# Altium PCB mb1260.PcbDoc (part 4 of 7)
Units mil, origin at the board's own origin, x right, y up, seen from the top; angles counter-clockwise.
Board outline 3189.01 x 3818.89 mil, 6 copper layers (TOP, L2_GND, L3_VCC, L4_SIG, L5_GND, BOTTOM), stack 62.2 mil thick; 308 components, 287 nets, 1220 pads, 851 vias.
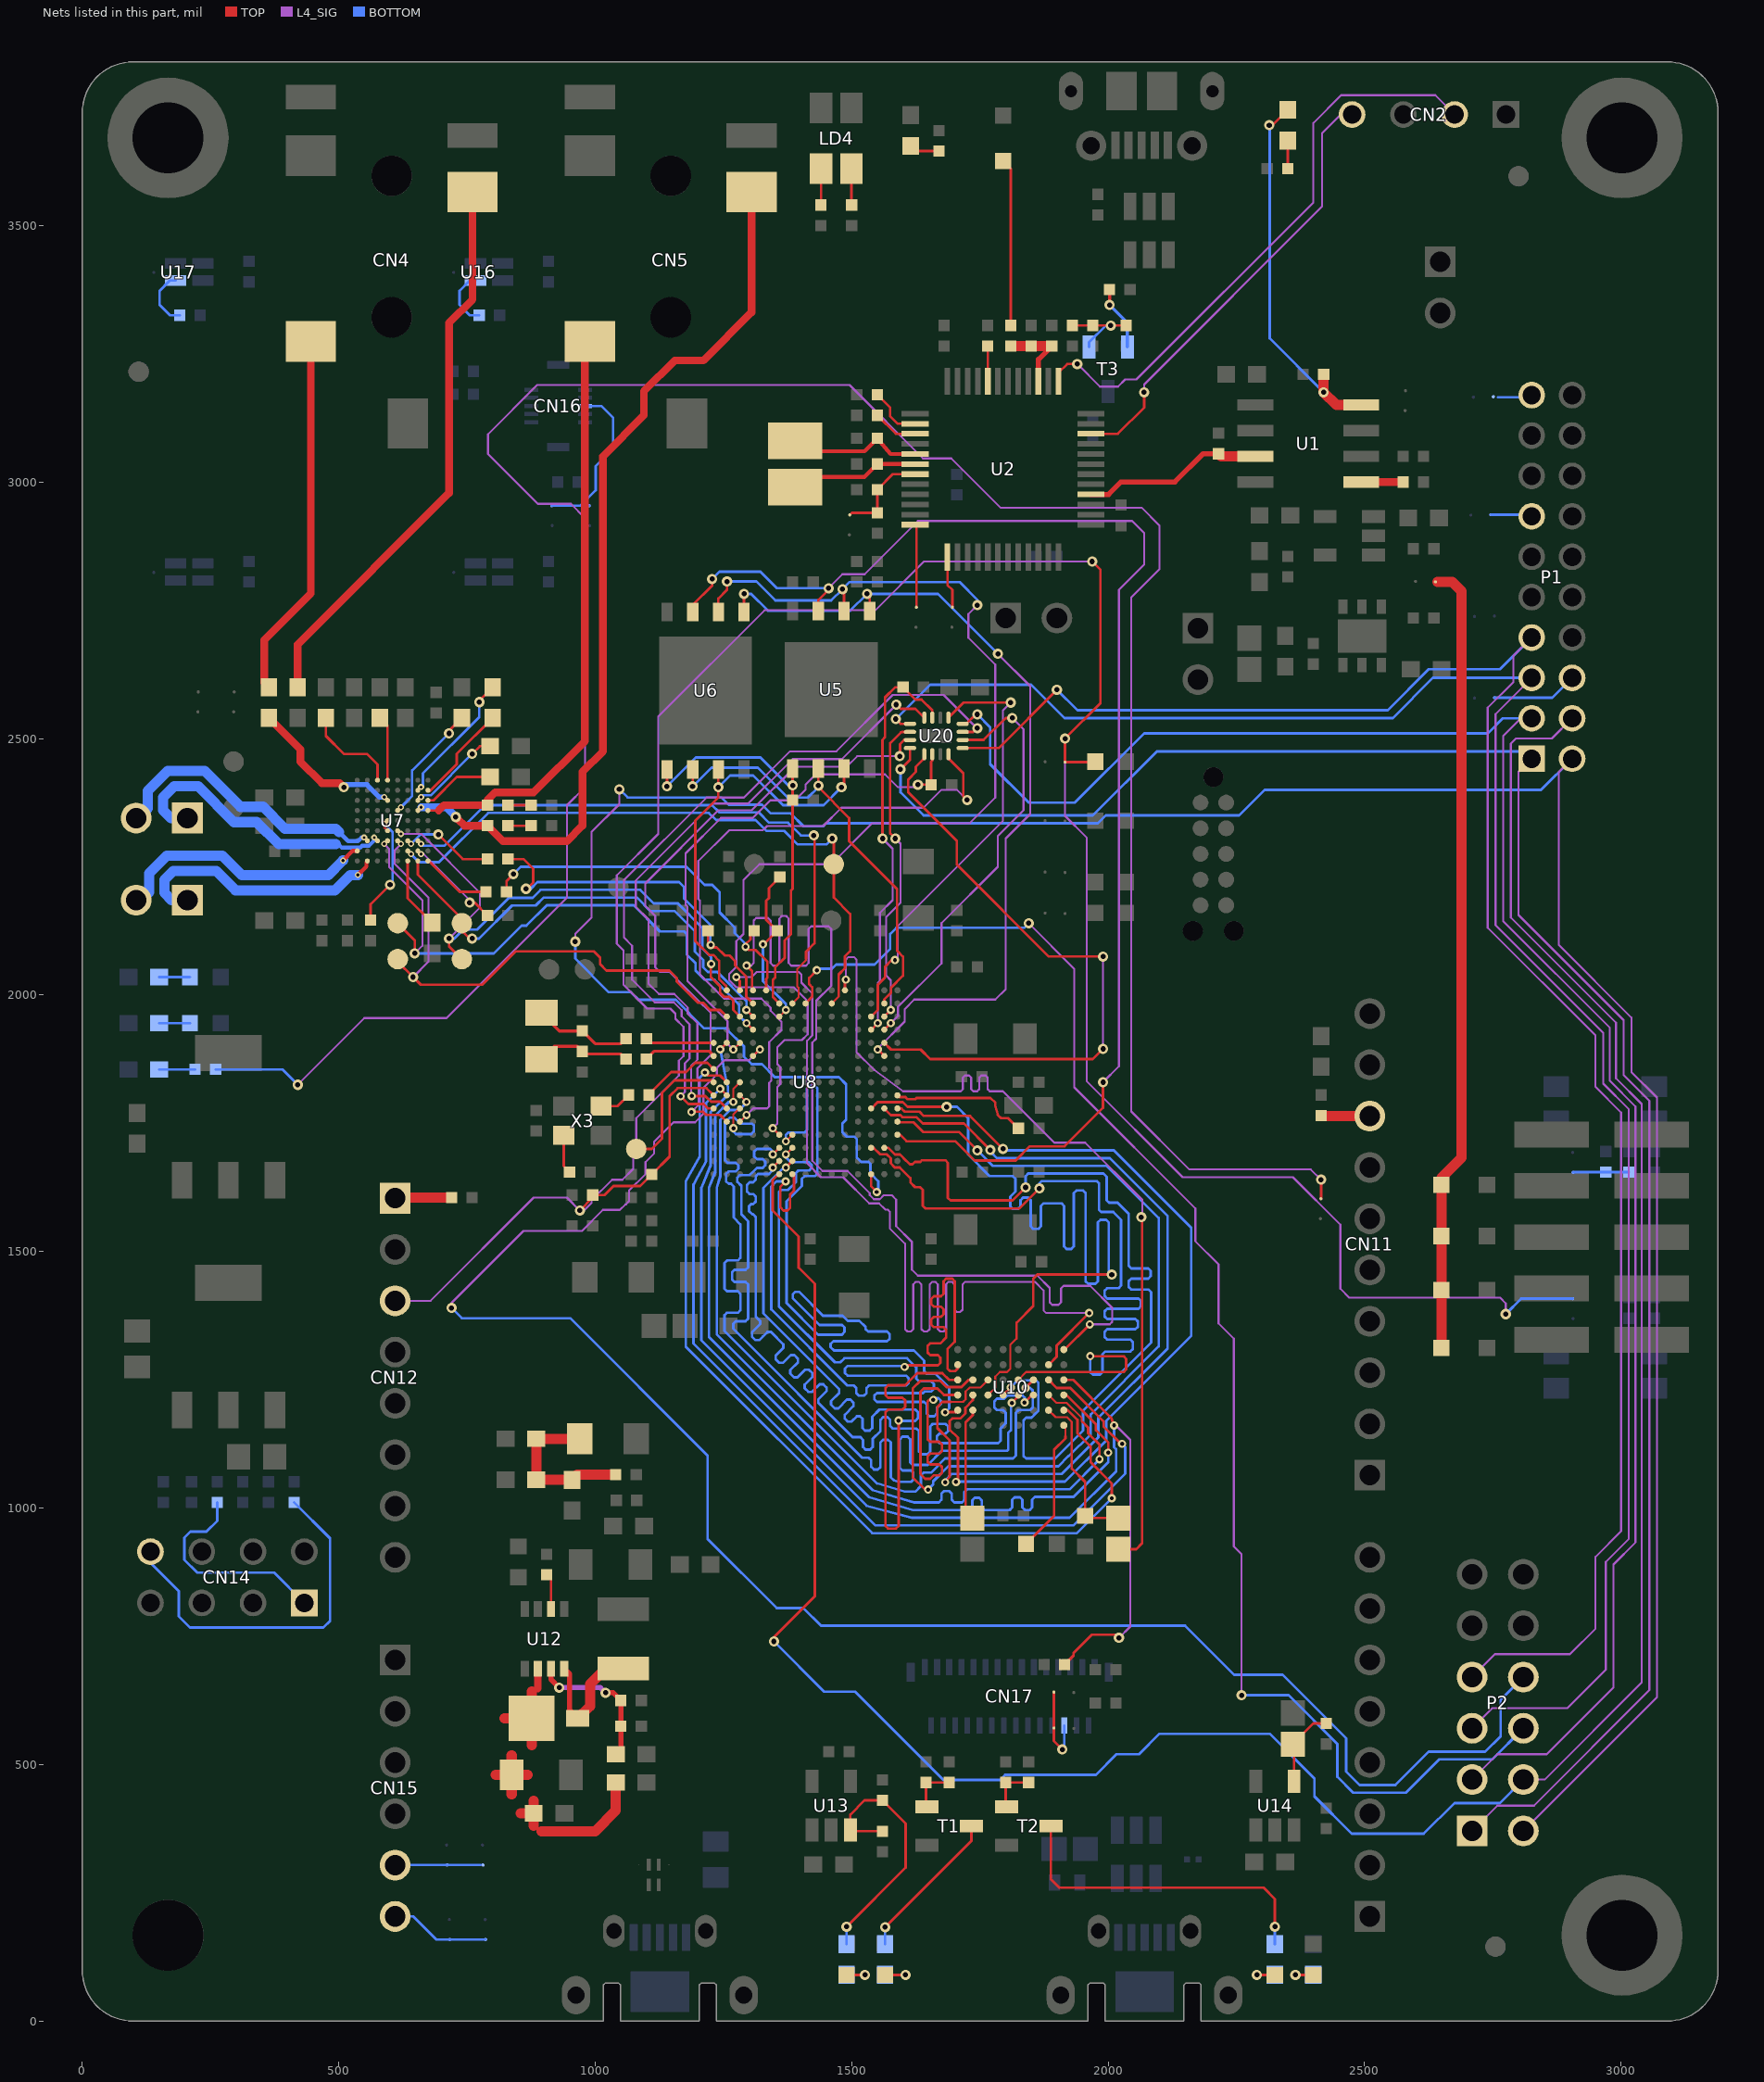
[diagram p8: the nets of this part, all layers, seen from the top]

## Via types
v1: diameter 24, hole 12, TOP to BOTTOM, tented both sides, 389 vias
v2: diameter 20, hole 10, TOP to BOTTOM, tented both sides, 231 vias
v3: diameter 16, hole 8, TOP to BOTTOM, tented both sides, 196 vias
v4: diameter 12, hole 6, TOP to BOTTOM, tented both sides, 35 vias

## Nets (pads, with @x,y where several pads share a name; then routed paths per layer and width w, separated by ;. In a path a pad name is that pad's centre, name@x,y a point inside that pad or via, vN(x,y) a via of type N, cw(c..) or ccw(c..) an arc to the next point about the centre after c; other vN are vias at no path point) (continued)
NETC18_2: C18.2 CN4.4 | length 1106.2
  TOP w15: C18.2@420,2600 420,2683.37 715,2978.37 715,3310 760.63,3355.63 CN4.4@760.63,3565.11
NETC19_2: C19.2 U7.C9 | length 189.2
  TOP w5: C19.2@475,2540 475,2505 510,2470 555,2470 575.47,2449.53 U7.C9@575.47,2418.74
NETC21_1: C21.1 U7.D9 | length 127.5
  TOP w5: C21.1@580,2540 595.16,2524.84 U7.D9@595.16,2418.74
NETC24_1: C24.1 U7.E6 | length 232.2
  TOP w5: U7.E6@614.84,2359.69 v4(621.14,2365.99) ; v2(715,2510) 715,2515 C24.1@740,2540
  BOTTOM w5: v4(621.14,2365.99) 643,2387.85 643,2438 v2(715,2510)
NETC25_1: C25.1 U7.H8 | length 196.2
  TOP w5: U7.H8@673.9,2399.06 679.06,2399.06 730,2450 730,2470 C25.1@800,2540
NETC25_2: C25.2 U7.G8 | length 261.3
  TOP w5: U7.G8@654.21,2399.06 v4(660.51,2405.36) ; v2(774,2571) 774,2574 C25.2@800,2600
  BOTTOM w5: v4(660.51,2405.36) 664.05,2408.9 664.05,2432.05 774,2542 v2(774,2571)
NETC26_1: C26.1 U7.G7 | length 184.5
  TOP w5: U7.G7@654.21,2379.37 v4(660.51,2385.67) ; v2(760,2470) 775,2485 C26.1@795,2485
  BOTTOM w5: v4(660.51,2385.67) 664.06,2389.22 679.22,2389.22 v2(760,2470)
NETC27_1: C27.1 U7.D7 | length 315.9
  TOP w5: v4(588.86,2385.67) U7.D7@595.16,2379.37
  TOP w15: C27.1@364,2540 425,2479 425,2455 467,2413 502,2413 v2(510,2405)
  BOTTOM w10: v2(510,2405) 515,2410 555,2410 579.33,2385.67 v4(588.86,2385.67)
NETC27_2: C27.2 CN4.6 | length 715.1
  TOP w15: C27.2@364,2600 355,2609 355,2692 445.67,2782.67 CN4.6@445.67,3273.78
NETC28_1: C28.1 U7.H7 | length 140
  TOP w5: U7.H7@673.9,2379.37 684.37,2379.37 730,2425 C28.1@795,2425
NETC30_1: C30.1 CN5.6 U7.H6 | length 1150.8
  TOP w5: U7.H6@673.9,2359.69 694.69,2359.69
  TOP w15: 694.69,2359.69 705,2370 C30.1@790,2370 790,2380 805,2395 880,2395 980,2495 980,3264.1 CN5.6@989.68,3273.78
NETC30_2: C30.2 R31.1 | length 45
  TOP w5: C30.2@830,2370 R31.1@875,2370
NETC32_1: C32.1 CN5.4 U7.G6 | length 1761.1
  TOP w5: U7.G6@654.21,2359.69 v4(660.51,2365.99)
  TOP w15: v2@732.57,2342.43 745,2330 C32.1@790,2330 820,2300 945,2300 975,2330 975,2435 1015,2475 1015,3050 1095,3130 1095,3177 1155,3237 1211,3237 1304.64,3330.64 CN5.4@1304.64,3565.11
  BOTTOM w15: v4(660.51,2365.99) 709.01,2365.99 v2(728,2347)
NETC32_2: C32.2 R33.1 | length 45
  TOP w5: C32.2@830,2330 R33.1@875,2330
NETC43_2: C43.2 U7.F1 | length 139.9
  TOP w5: U7.F1@634.53,2261.26 634.53,2188.47 C43.2@682,2141
NETC48_2: C48.2 R49.1 X2.1 | length 194.1
  TOP w6: X2.1@895,1965.28 930.28,1930 C48.2@975,1930 1000,1905 1050,1905 R49.1@1060,1915
NETC51_2: C51.2 R50.1 X2.2 | length 185.8
  TOP w6: X2.2@895,1874.72 920.28,1900 965,1900 C51.2@975,1890 980,1885 1050,1885 R50.1@1060,1875
NETC67_1: C67.1 C69.2 L2.2 L3.2 L4.1 | length 324.1
  TOP w20: C67.1@970,1135 L2.2@885,1135 L3.2@885,1055 L4.1@955,1055 965,1065 C69.2@1040,1065
NETC75_2: C75.2 C76.2 L8.1 U12.6 Z1.2 | length 625
  TOP w15: 888.2,648.2 U12.6@888.2,686.93
  TOP w20: 805.98,480 C75.2@837,480 ; 822.98,590 Z1.2@876,590 ; 837,441.98 C75.2@837,480 ; 837,518.02 C75.2@837,480 ; 854.48,405 C76.2@880,405 ; 868.02,480 C75.2@837,480 ; 876,537.48 Z1.2@876,590 ; 876,642.52 Z1.2@876,590 ; 880,380.98 C76.2@880,405 ; 880,429.02 C76.2@880,405 ; 895,370 1000,370 1040,410 L8.1@1040,465
NETC86_2: C86.2 R90.1 SB33.2 | length 109.2
  BOTTOM w5: SB33.2@2906.19,1654.17 2907.02,1655 C86.2@2970,1655 R90.1@3015,1655
NETCN7_1: CN7.1 U7.C3 | length 568.3
  TOP w5: v4(569.17,2306.93) U7.C3@575.47,2300.63
  BOTTOM w8: 494.4,2294.1 496.79,2294.1 ; 497.4,2293.49 499.59,2293.49 506.05,2287.03 542.03,2287.03 545.66,2290.66 558.54,2290.66 569.17,2301.29 v4(569.17,2306.93)
  BOTTOM w20: CN7.1@205,2345 172.57,2345 157.79,2359.78 157.79,2385.42 179.06,2406.69 226.31,2406.69 296,2337 340,2337 382.9,2294.1 494.4,2294.1
NETCN7_2: CN7.2 U7.B3 | length 570.6
  TOP w5: v4(549.49,2306.93) U7.B3@555.79,2300.63
  BOTTOM w8: 501,2317.4 518.43,2299.97 537.49,2299.97 544.45,2306.93 v4(549.49,2306.93)
  BOTTOM w20: CN7.2@105,2345 108.91,2345 127.89,2363.98 127.89,2397.81 166.67,2436.59 238.7,2436.59 308.39,2366.9 352.39,2366.9 395.29,2324 494.4,2324 501,2317.4
NETCN10_1: CN10.1 U7.B1 | length 524.1
  TOP w8: v4(537.4,2233.87) 553.9,2250.37 553.9,2259.37 U7.B1@555.79,2261.26
  BOTTOM w20: CN10.1@205,2185 174,2185 160,2199 160,2224.71 177.29,2242 261,2242 298.9,2204.1 492.48,2204.1 522.25,2233.87 v4(537.4,2233.87)
NETCN10_2: CN10.2 U7.A2 | length 524
  TOP w8: v4(508.35,2262.34) 526.95,2280.94 U7.A2@536.1,2280.94
  BOTTOM w20: CN10.2@105,2185 115,2185 130.1,2200.1 130.1,2237.1 164.9,2271.9 273.39,2271.9 311.29,2234 480.09,2234 v4(508.35,2262.34) v4(508.35,2262.34)
NETCN11_8: CN11.8 R53.1 | length 95.3
  TOP w20: R53.1@2415,1765 2416.06,1763.94 CN11.8@2509.84,1763.94
NETCN12_1: CN12.1 R58.1 | length 110.6
  TOP w20: CN12.1@609.84,1603.94 610.9,1605 R58.1@720,1605
NETCN14_1: CN14.1 R92.2 | length 425.5
  BOTTOM w5: R92.2@263,1011 263,975 242,954 211,954 199,942 199,899 224,874 373.99,874 CN14.1@432.99,815
NETCN14_8: CN14.8 R97.1 | length 718.3
  BOTTOM w5: CN14.8@132.99,915 132.99,893.01 188,838 188,789 210,767 470,767 483,780 483,941 R97.1@413,1011
NETCN15_5: CN15.5 SB35.2 SB36.2 | length 166.4
  BOTTOM w5: CN15.5@609.84,303.94 610.07,304.17 SB36.2@711.19,304.17 776.19,304.17
NETCN15_6: CN15.6 SB37.2 SB38.2 | length 195.2
  BOTTOM w5: CN15.6@609.84,203.94 645,203.94 689.91,159.03 SB38.2@716.39,159.03 SB37.2@786.39,159.03
NETCN16_8: CN16.8 SB2.1 SB4.1 | length 335.5
  BOTTOM w5: SB2.1@915.17,2953.77 970.85,2953.77 ; CN16.8@979.91,3148.16 1011.84,3148.16 1035,3125 1035,3065 1000.84,3030.84 1000.84,2983.76 970.85,2953.77 ; SB4.1@988.17,2953.77 970.85,2953.77
NETCN17_24: CN17.24 SB15.2 SB16.2 | length 166.6
  TOP w5: SB15.2@1894.17,641.19 SB16.2@1894.17,571.19 1894.17,545.83 v2(1910.55,529.45)
  BOTTOM w5: v2(1910.55,529.45) 1914.45,533.35 CN17.24@1914.45,575.91
NETD1_2: D1.2 R4.2 | length 326.9
  TOP w5: D1.2@1795,3625.71 1810,3610.71 R4.2@1810,3305
NETD2_2: D2.2 D3.2 D4.2 D5.2 SB7.1 | length 1545.5
  TOP w20: 2642.33,2805.33 2670.67,2805.33 2689,2787 2689,1683 2649.71,1643.71 D5.2@2649.71,1630 D4.2@2649.71,1530 D3.2@2649.71,1425 D2.2@2649.71,1312
NETL6_2: L6.2 U12.8 Z1.1 | length 262.3
  TOP w10: U12.8@939.39,686.93 950,676.32 950,606 Z1.1@966,590
  TOP w20: Z1.1@966,590 990,614 990,657 1020,687 L6.2@1055,687
NETL7_2: L7.2 R69.2 R71.2 U12.7 | length 283.1
  TOP w10: U12.7@913.8,686.93 913.8,666.2 v2(930,650) ; v2(1020,640) 1035,640 R69.2@1050,625 R71.2@1050,575 1050,530 L7.2@1040,520
  L4_SIG w10: v2(930,650) 1010,650 v2(1020,640)
NETLD1_1: LD1.1 R12.1 | length 70
  BOTTOM w5: LD1.1@150,1855 R12.1@220,1855
NETLD2_1: LD2.1 R1.2 | length 59.1
  TOP w5: LD2.1@1615,3655 1625,3645 R1.2@1670,3645
NETLD3_1: LD3.1 R2.1 | length 55
  TOP w5: R2.1@2350,3610.59 LD3.1@2350,3665.59
NETLD3_2: LD3.2 R15.1 U1.8 | length 731.6
  TOP w5: v2(2314,3695.59) 2320,3695.59 LD3.2@2350,3725.59
  TOP w20: R15.1@2420,3210 v2(2420,3175) 2445,3150 U1.8@2493.3,3150
  BOTTOM w5: v2(2314,3695.59) 2315,3694.59 2315,3280 v2(2420,3175)
NETLD4_2: LD4.2 R14.2 | length 71.1
  TOP w5: LD4.2@1499.53,3610.94 1499.53,3540.47 R14.2@1500,3540
NETLD4_3: LD4.3 R13.2 | length 71.1
  TOP w5: R13.2@1440,3540 1440.47,3540.47 LD4.3@1440.47,3610.94
NETLD5_1: LD5.1 R47.2 | length 60
  BOTTOM w5: LD5.1@150,2035 R47.2@210,2035
NETLD6_1: LD6.1 R48.2 | length 60
  BOTTOM w5: LD6.1@150,1945 R48.2@210,1945
NETLD7_1: LD7.1 R81.2 | length 72
  TOP w5: R81.2@1490,90 v2(1526,90)
  BOTTOM w5: LD7.1@1490,90 v2(1526,90)
NETLD7_2: LD7.2 R78.1 R80.2 U13.3 | length 513.9
  TOP w5: v2(1490,184) 1605,299 1605,385 R78.1@1560,430 1525,430 1497.4,402.4 U13.3@1497.4,372.76 1499.33,370.38 1499.64,370 R80.2@1560,370
  BOTTOM w5: LD7.2@1490,150 v2(1490,184)
NETLD8_1: LD8.1 R82.1 | length 80
  TOP w5: R82.1@1565,90 v2(1605,90)
  BOTTOM w5: LD8.1@1565,90 v2(1605,90)
NETLD8_2: LD8.2 T1.3 | length 299.7
  TOP w5: v2(1565,183) 1733.31,351.31 T1.3@1733.31,380
  BOTTOM w5: LD8.2@1565,150 v2(1565,183)
NETLD9_1: LD9.1 R83.1 | length 70
  TOP w5: v2(2290,90) R83.1@2325,90
  BOTTOM w5: v2(2290,90) LD9.1@2325,90
NETLD9_2: LD9.2 T2.3 | length 644
  TOP w5: T2.3@1888.31,380 1888.31,276.69 1905,260 2303,260 2325,238 v2(2325,184)
  BOTTOM w5: LD9.2@2325,150 v2(2325,184)
NETLD10_1: LD10.1 R84.1 | length 70
  TOP w5: v2(2365,90) R84.1@2400,90
  BOTTOM w5: v2(2365,90) LD10.1@2400,90
NETR3_2: R3.2 U2.44 | length 68.9
  TOP w5: R3.2@1765,3265 1765.47,3264.53 U2.44@1765.47,3196.26
NETR7_1: R7.1 R8.2 R11.2 T3.1 | length 170.1
  TOP w5: R7.1@1930,3305 R8.2@1970,3305 v2(2005,3305) R11.2@2035,3305
  BOTTOM w5: T3.1@1962.6,3263.31 1962.6,3272.6 1995,3305 v2(2005,3305)
NETR10_1: R10.1 T3.2 | length 126.1
  TOP w6.1: v2(2002.6,3345) R10.1@2002.6,3375
  BOTTOM w6.1: v2(2002.6,3345) 2037.4,3310.2 T3.2@2037.4,3263.31
NETR12_2: R12.2 SB14.1 | length 4971.4
  TOP w5: SB14.1@2415,1603.01 v2(2415,1640)
  L4_SIG w4: v2(420,1825) 550,1955 710,1955 945,2190 945,2370 980,2405 980,2930 952.67,2957.33 888.13,2957.33 790.94,3054.52 790.94,3092.96 886.98,3189 1496,3189 1639,3046 1694,3046 1790,2950 2065,2950 2100,2915 2100,2830 2045,2775 2045,1773 2158,1660 2395,1660 v2(2415,1640)
  BOTTOM w5: R12.2@260,1855 390,1855 v2(420,1825)
NETR17_2: R17.2 U2.2 | length 107.1
  TOP w5: R17.2@1550,3170 1575,3145 1575,3128 1589.42,3113.58 U2.2@1623.74,3113.58
NETR19_2: R19.2 U2.3 | length 88.7
  TOP w5: R19.2@1550,3130 1586.1,3093.9 U2.3@1623.74,3093.9
NETR22_1: R22.1 U1.5 | length 81.7
  TOP w15: U1.5@2493.3,3000 R22.1@2575,3000
NETR35_2: R35.2 U7.F3 | length 185.7
  TOP w5: U7.F3@634.53,2300.63 v4(640.83,2294.33) ; v2(694,2313) 742,2265 R35.2@790,2265
  BOTTOM w5: v4(640.83,2294.33) 659.5,2313 v2(694,2313)
NETR39_2: R39.2 U7.H1 | length 138.1
  TOP w5: U7.H1@673.9,2261.26 675.15,2260.01 676.68,2260.01 735.69,2201 R39.2@787,2201
NETR41_2: R41.2 U7.G2 | length 191
  TOP w5: U7.G2@654.21,2280.94 v4(660.51,2274.64) ; v2(755,2180) 765,2180 R41.2@790,2155
  L4_SIG w4: v4(660.51,2274.64) 665.52,2274.64 755,2185.16 v2(755,2180)
NETR46_1: R46.1 U7.D4 U7.D5 | length 237.1
  TOP w5: R46.1@562,2146 562,2177 v2(600,2215) ; U7.D4@595.16,2320.31 588.85,2326.62 v4(588.85,2333.7) U7.D5@595.16,2340
  BOTTOM w5: v4(588.85,2333.7) 605,2317.55 605,2220 v2(600,2215)
NETR55_2: R55.2 X3.1 | length 76.2
  TOP w5: X3.1@938.58,1726.46 938.58,1666.42 R55.2@950,1655
NETR63_1: R63.1 R65.2 U10.B5 | length 315.2
  TOP w4: U10.B5@1883.82,1190.71 1897.53,1177 1920,1177 1929,1168 1929,1145
  TOP w5: 1929,1145 1929,1077 1955,1051 R63.1@1955,985 1959.49,980.51 R65.2@2020,980.51
NETR64_2: R64.2 U10.G5 | length 221.5
  TOP w5: R64.2@1735,980.51 1722,993.51 1722,1167 1736.18,1181.18 U10.G5@1736.18,1190.71
NETR67_2: R67.2 U12.2 | length 70.6
  TOP w5: R67.2@905,870 913.8,861.2 U12.2@913.8,803.07
NETR72_2: R72.2 R73.1 U14.4 | length 155.3
  TOP w5: U14.4@2362.4,467.24 2362.4,537.09 R72.2@2360,539.49 2360,540 2400,580 R73.1@2425,580
NETR74_1: R74.1 R75.1 T1.1 | length 93.3
  TOP w5: T1.1@1646.69,417.4 1645,419.09 R74.1@1645,465 R75.1@1690,465
NETR76_2: R76.2 R77.1 T2.1 | length 93.3
  TOP w5: T2.1@1801.69,417.4 1800,419.09 R76.2@1800,465 R77.1@1845,465
NETR85_1: R85.1 U16.2 | length 113.7
  BOTTOM w5: U16.2@766.5,3392.68 755.29,3392.68 735.29,3372.68 735.29,3345.32 755.61,3325 R85.1@773.74,3325
NETR86_1: R86.1 U17.2 | length 114.6
  BOTTOM w5: U17.2@181.89,3392.68 170.68,3392.68 150.68,3372.68 150.68,3345.32 171,3325 R86.1@190,3325
NETR100_1: R100.1 U10.A6 | length 264.2
  TOP w4: U10.A6@1913.35,1161.18 1916.5,1158.03 1916.5,1140
  TOP w5: R100.1@1840,930 1894.51,984.51 1894.51,1113.51 1916.5,1135.5 1916.5,1140
NRST: C93.2 CN12.3 R28.2 R57.1 SB10.2 SB34.1 U8.J1 | length 5444.3
  TOP w5: v2(970,1580) 995,1605 C93.2@995,1610 1018.17,1610 1035.67,1627.5 1087.5,1627.5 R57.1@1110,1650 1145,1685 1145,1803 1160.5,1818.5 1216.78,1818.5 U8.J1@1230.87,1804.41 ; v2(1969,2845) 1985,2829 1985,2569.17 v2(1915.83,2500) SB10.2@1915.83,2453.81 1973.81,2453.81 R28.2@1975,2455
  L4_SIG w4: CN12.3@609.84,1403.94 678.94,1403.94 880,1605 945,1605 v2(970,1580) 978.02,1580 993,1594.98 993,1599.98 1033.02,1640 1053.1,1640 1074.03,1660.93 1074.03,1684.09 1080,1690.06 1080,1760 1163,1843 1163,1871.94 1172,1880.94 1172,1938 1156.35,1953.65 1156.35,1963.78 1146.4,1973.73 1101.27,1973.73 1055,2020 1055,2087 1042,2100 1042,2233 1123,2314 1123,2543 1330,2750 1546,2750 1641,2845 v2(1969,2845) ; v2(1915.83,2500) 1915.83,2349.17 1958,2307 1958,1832 2145,1645 2360,1645 2452.5,1552.5 2452.5,1427.5 2470,1410 2764,1410 2775,1399 v2(2775,1378)
  BOTTOM w5: v2(2775,1378) 2805.01,1408.01 SB34.1@2905.33,1408.01
OSC_25M: R51.1 X3.3 | length 62.5
  TOP w5: X3.3@1011.42,1783.54 1043.54,1783.54 R51.1@1065,1805
OSC_IN: C4.2 U2.5 X1.2 | length 266.7
  TOP w8: X1.2@1390,3080.28 1410.28,3060 1525,3060 C4.2@1550,3085 1575.47,3054.53 U2.5@1623.74,3054.53
OSC_OUT: C6.2 U2.6 X1.1 | length 252.5
  TOP w8: X1.1@1390,2989.72 1410,3009.72 1524.72,3009.72 C6.2@1550,3035 1554.84,3034.84 U2.6@1623.74,3034.84
PC14-OSC32_IN: R49.2 U8.E1 | length 134.3
  TOP w6: R49.2@1100,1915 1108.23,1906.77 U8.E1@1230.87,1906.77
PC15-OSC32_OUT: R50.2 U8.F1 | length 141.2
  TOP w6: R50.2@1100,1875 1115.5,1890.5 1221.55,1890.5 U8.F1@1230.87,1881.18
PDRON: R37.2 R45.2 U8.C6 | length 328.5
  TOP w4: U8.C6@1358.82,1957.95 v3(1371.68,1970.81)
  TOP w5: v3(1327,2099) 1329,2099 R45.2@1355,2125 1333.5,2146.5 1333.5,2183.91 1338.5,2188.91 1338.5,2208.5 R37.2@1360,2230
  BOTTOM w5: v3(1327,2099) 1327,2027 1371.68,1982.32 v3(1371.68,1970.81)
PH0-OSCIN: R51.2 U8.G1 | length 158.1
  TOP w5: R51.2@1105,1805 1105,1806.71 1148.29,1850 1177,1850 1195,1868 1218.46,1868 U8.G1@1230.87,1855.59
PH1-OSCOUT: TP15.1 U8.H1 | length 259.9
  TOP w5: TP15.1@1080,1700 1110,1700 1130,1720 1130,1809.22 1154.28,1833.5 1227.37,1833.5 U8.H1@1230.87,1830
PMOD#1: P1.1 P2.1 U20.8 | length 3792.3
  TOP w5: v2(1595,2440) 1613.63,2458.63 U20.8@1613.63,2481.38
  L4_SIG w4: P2.1@2709.33,370.63 2758.7,420 2830,420 3055,645 3055,1793.78 3005,1843.78 3005,1951 2800,2156 2800,2435 P1.1@2825.63,2460.63
  BOTTOM w5: v2(1595,2440) 1595,2395 1640,2350 1970,2350 2095,2475 2811.26,2475 P1.1@2825.63,2460.63
PMOD#2: P1.2 P2.2 U20.16 | length 3697.9
  TOP w5: U20.16@1716.37,2528.62 1723.62,2528.62 1742,2547 v2(1745,2547)
  L4_SIG w4: P2.2@2709.33,470.63 2758.7,520 2855,520 2985,650 2985,890 3028,933 3028,1782.58 2978,1832.58 2978,1936 2770,2144 2770,2505 2804.37,2539.37 P1.2@2825.63,2539.37
  BOTTOM w5: v2(1745,2547) 1770,2522 1770,2450 1845,2375 1935,2375 2070,2510 2740,2510 2769.37,2539.37 P1.2@2825.63,2539.37
PMOD#3: P1.3 P2.3 U20.5 | length 3754.9
  TOP w5: v2(1586,2538) 1595.38,2528.62 U20.5@1613.63,2528.62
  L4_SIG w4: P2.3@2709.33,570.63 2748.7,610 2895,610 2970,685 2970,895 3015,940 3015,1777.19 2965,1827.19 2965,1926 2755,2136 2755,2547.48 P1.3@2825.63,2618.11
  BOTTOM w5: v2(1586,2538) 1653,2605 1850,2605 1915,2540 2555,2540 2633.11,2618.11 P1.3@2825.63,2618.11
PMOD#4: P1.4 P2.4 U20.13 | length 3607.1
  TOP w5: U20.13@1716.37,2481.38 1786.38,2481.38 v2(1900,2595)
  L4_SIG w4: P2.4@2709.33,670.63 2753.7,715 2900,715 2950,765 2950,905 3000,955 3000,1770.97 2950,1820.97 2950,1921 2740,2131 2740,2560 2790,2610 2790,2661.22 P1.4@2825.63,2696.85
  BOTTOM w5: v2(1900,2595) 1940,2555 2545,2555 2625,2635 2763.78,2635 P1.4@2825.63,2696.85
PMOD_GPIO_0: P2.9 U8.B8 | length 2941.3
  TOP w5: U8.B8@1410,1983.54 1423,1996.54 1423,2015 1417,2021 1417,2033 1431.98,2047.98 v3(1431.98,2048.39)
  L4_SIG w4: v2(1845,2140) 1934,2051 1934,1820 2170,1584 2170,1520 2215,1475 2215,1360 2245,1330 2245,925 2260,910 v2(2260,635)
  BOTTOM w5: v3(1431.98,2048.39) 1432.61,2048.39 1435.22,2051 1461,2051 1469.5,2059.5 1544.5,2059.5 1575,2090 1575,2119 1587,2131 1836,2131 v2(1845,2140) ; v2(2260,635) 2352,635 2447,540 2447,476 2478,445 2580,445 2645,510 2748.7,510 P2.9@2809.33,570.63
PMOD_GPIO_1: P2.10 U8.F4 | length 3647.6
  TOP w5: U8.F4@1307.64,1881.18 1308.18,1881.18 v3(1321,1894)
  L4_SIG w4: v2(720,1390) 720,1400 860,1540 974.14,1540 1015.14,1581 1047.88,1581 1059,1592.12 1060,1592.12 1066,1598.12 1066,1618.94 1098.03,1650.97 1098.03,1674.13 1115,1691.1 1115,1714.27 1152.73,1752 1194.61,1752 1211,1768.39 1211,1819 1237,1845 1237,1858 1252,1873 1256.36,1873 1262.99,1873.01 1300,1873 v3(1321,1894)
  BOTTOM w5: v2(720,1390) 740,1370 951,1370 1219,1102 1219,939.78 1353.78,805 1405.78,805 1440.28,770.5 2150,770.5 2245.5,675 2340,675 2464,551 2464,486 2490,460 2560,460 2625,525 2735,525 2765,555 2765,626.3 P2.10@2809.33,670.63
PMOD_INT: P1.11 P2.7 U8.R13 | length 5536.4
  TOP w5: U8.R13@1537.95,1650.87 1537.95,1627.05 v3(1549,1616)
  L4_SIG w4: v2(961,2104) 961,2119 993,2151 993,2318 1047,2372 v2(1047,2401) ; P2.7@2809.33,370.63 3070,631.3 3070,1800 3020,1850 3020,1956 2878.37,2097.63 2878.37,2434.63 P1.11@2904.37,2460.63
  BOTTOM w5: v2(961,2104) 961,2071 1026.5,2005.5 1069.5,2005.5 1084.5,1990.5 1157.06,1990.5 1212.57,1934.99 1255.01,1934.99 1290,1900 1290,1880 1305,1865 1325,1865 1350,1840 1475,1840 1489,1826 1489,1757 1482,1750 1482,1732 1490,1724 1505,1724 1510,1719 1510,1683 1518.31,1674.69 1532.55,1674.69 1536.24,1671 1536.24,1652.76 1552,1637 1552,1619 v3(1549,1616) ; v2(1047,2401) 1063,2385 1246,2385 1260,2371 1325.08,2371 1342.08,2354 1381,2354 1406.04,2328.96 1443.96,2328.96 1450,2335 1980,2335 1995,2350 2255,2350 2305,2400 2843.74,2400 P1.11@2904.37,2460.63
PMOD_RESET: P1.12 P2.8 U8.R6 | length 5124.8
  TOP w5: v2(1348.53,740) 1348.53,748.53 1428,828 1428,1437 1396.5,1468.5 1396.5,1529.16 1346,1579.66 1346,1639.18 1358.82,1652 U8.R6@1358.82,1650.87
  L4_SIG w4: P2.8@2809.33,470.63 2850.63,470.63 3040,660 3040,1787.56 2990,1837.56 2990,1946 2785,2151 2785,2490 2795,2500 2865,2500 P1.12@2904.37,2539.37
  BOTTOM w5: v2(1348.53,740) 1446.53,642 1506.78,642 1678.78,470 1789,470 1799,480 1976.22,480 2016.22,520 2060,520 2100,560 2315,560 2402,473 2402,438 2475,365 2615,365 2675,425 2763.7,425 P2.8@2809.33,470.63
PMOD_SEL_0: R102.1 U8.D13 U20.3 | length 808.9
  TOP w5: U8.D13@1537.95,1932.36 v3(1550.81,1945.22) ; v2(1560,2305) 1560,2497.44 1565,2502.44 1565,2580 1585,2600 R102.1@1600,2600 1624,2576 1636.13,2576 1657.13,2555 U20.3@1657.13,2540.62
  L4_SIG w4: v3(1550.81,1945.22) 1550.81,2023.47 1555,2027.66 1555,2160 1580,2185 1580,2285 v2(1560,2305)
PMOD_SEL_1: R29.2 U8.E3 U20.10 | length 1063.8
  TOP w4: v3(1269.13,1893.97) 1268.68,1893.97 1268.68,1893.52 1268.96,1893.52 1282.05,1906.61 U8.E3@1282.05,1906.77
  TOP w5: v2(1629,2410) R29.2@1655,2410 1655,2455 1657.13,2457.13 U20.10@1657.13,2469.38
  L4_SIG w4: v3(1269.13,1893.97) 1258,1905.1 1258,1949 1180,2027 1180,2172 1176,2176 1176,2276 1245,2345 1306.98,2345 1341.44,2379.46 1389.46,2379.46 1410,2400 1410,2410 1430,2430 1565,2430 1590,2405 1625,2405 1630,2410 v2(1629,2410)
PMOD_SPI2_MISO: U8.C14 U20.6 | length 609.8
  TOP w5: U8.C14@1563.54,1957.95 1576.04,1970.45 1576.04,1970.58 v3(1576.25,1970.79) ; v2(1585,2305) 1575,2315 1575,2491.22 1595.91,2512.13 1597.13,2512.13 1597.87,2512.87 U20.6@1613.63,2512.87
  L4_SIG w4: v3(1576.25,1970.79) 1576.25,2028.75 1567,2038 1567,2152 1595,2180 1595,2295 v2(1585,2305)
PMOD_SPI2_MOSI: U8.C13 U20.1 | length 861.9
  TOP w5: U8.C13@1537.95,1957.95 1551.04,1971.04 1551.04,2020.04 1565,2034 1565,2054.75 1570,2059.75 1570,2060 1578.25,2068.25 v3(1584.37,2068.25) ; U20.1@1688.62,2540.62 1718,2570 v2(1810,2570)
  L4_SIG w4: v3(1584.37,2068.25) 1590,2073.88 1590,2135 1795,2340 1795,2555 v2(1810,2570)
PMOD_SPI2_NSS: U8.E14 U20.9 | length 1254.8
  TOP w5: U8.E14@1563.54,1906.77 1576.63,1893.68 1634.49,1893.68 1653.17,1875 1970,1875 v2(1990,1895) ; U20.9@1641.38,2469.38 1641.38,2461.38 1625,2445 1625,2435 1610,2420 1610,2395 1705,2300 1705,2254 1884,2075 v2(1990,2075)
  L4_SIG w4: v2(1990,1895) v2(1990,2075)
PMOD_SPI2_SCK: U8.D14 U20.14 | length 843.6
  TOP w5: U8.D14@1563.54,1932.36 v3(1576.27,1945.09) ; U20.14@1716.37,2497.13 1757.13,2497.13 1800,2540 v2(1813,2540)
  L4_SIG w4: v3(1576.27,1945.09) 1590.25,1959.07 1590.25,1977.01 1675,2061.76 1675,2140 1785,2250 1785,2310 1835,2360 1835,2518 v2(1813,2540)
PMOD_UART7_CTS: U8.L2 U20.7 | length 1250.2
  TOP w5: v3(1187.77,1772) 1188.48,1772 1188.98,1772.5 1210.23,1772.5 1216.41,1766.32 1243.37,1766.32 U8.L2@1256.46,1753.23 ; v2(1593.67,2465.52) 1594.13,2465.98 1594.13,2489.13 1602.13,2497.13 U20.7@1613.63,2497.13
  L4_SIG w4: v3(1187.77,1772) 1202,1786.23 1202,1835 1199,1838 1199,1857 1225,1883 1225,1965.8 1211.8,1979 1211,1979 1145,2045 1126,2045 1117,2054 1117,2154 1097.51,2173.49 1097.51,2217.51 1240,2360 1305,2360 1390,2445 1490,2445 1510.52,2465.52 v2(1593.67,2465.52)
PMOD_UART7_RTS: U8.L3 U20.12 | length 1364.6
  TOP w4: U8.L3@1282.05,1753.23 1294.78,1765.96 v3(1294.91,1765.96)
  TOP w5: U20.12@1688.62,2469.38 1688.62,2461.38 1717.5,2432.5 1717.5,2387.5 v2(1725,2380)
  L4_SIG w4: v3(1294.91,1765.96) 1308.08,1779.13 1335,1779.13 1339,1783.13 1339,1828.68 1343,1832.68 1343,1854.56 1339,1858.56 1339,1908 1363,1932 1363,1947.98 1341.68,1969.3 1341.68,1975.32 1324,1993 1251,1993 1204,2040 1204,2184.12 1201,2187.12 1201,2261 1261,2321 1326.54,2321 1335,2329.46 1444.46,2329.46 1480,2365 1640,2365 1675,2400 1705,2400 v2(1725,2380)
PMOD_UART7_RXD: U8.K2 U20.4 | length 1286.1
  TOP w5: v3(1188,1803) 1214.6,1803 1225.69,1791.91 1243.37,1791.91 U8.K2@1256.46,1778.82 ; v2(1587,2566) 1595,2558 1624,2558 U20.4@1641.38,2540.62
  L4_SIG w4: v3(1188,1803) 1187,1804 1187,1861.98 1199,1873.98 1199,1945 1180.35,1963.65 1180.35,1975.61 1153.96,2002 1124,2002 1104,2022 1104,2147 1079,2172 1079,2223 1229,2373 1298,2373 1385,2460 1481,2460 v2(1587,2566)
PMOD_UART7_TXD: U8.K1 U20.15 | length 1474.7
  TOP w5: v3(1166.47,1802.53) 1181.5,1787.5 1211.32,1787.5 1220,1778.82 U8.K1@1230.87,1778.82 ; U20.15@1716.37,2512.87 1736.87,2512.87 1744,2520 v2(1745,2520)
  L4_SIG w4: v3(1166.47,1802.53) 1173,1809.06 1173,1809.22 1175,1811.22 1175,1866.96 1184,1875.96 1184,1943 1168.35,1958.65 1168.35,1970.63 1153.25,1985.73 1116.27,1985.73 1072,2030 1072,2096 1056,2112 1056,2224 1217,2385 1290,2385 1380,2475 1470,2475 1580,2585 1679,2585 1744,2520 v2(1745,2520)
PSRAM_A0: R101.1 U8.E2 U10.A3 | length 2391.5
  TOP w5: v3(1243.73,1894.04) U8.E2@1256.46,1906.77 ; U10.A3@1913.35,1249.76 1932.24,1249.76 2005.5,1176.5 v3(2011.5,1161) ; R101.1@1915,695 1932.5,712.5 1932.5,717.5 1968,753 2015,753 v2(2021.02,746.98)
  L4_SIG w4: v3(2011.5,1161) 2015,1161 2043,1133 2043,768.96 v2(2021.02,746.98)
  BOTTOM w5: v3(1243.73,1894.04) 1255,1834 1259,1821.2 1259,1806 1225,1772 1225,1668 1207.03,1624.79 1206.7,1624 1206.7,1326.86 1529.28,1004.28 1617,981 1925,981 2015.5,1071.5 2015.5,1114.43 2011.5,1118.43 v3(2011.5,1161)
PSRAM_A1: U8.H3 U10.A4 | length 1727.7
  TOP w4: v3(1269.13,1791.62) 1269.13,1817.08 U8.H3@1282.05,1830
  TOP w5: U10.A4@1913.35,1220.24 1918.76,1220.24 1976,1163 1976,1152 2000,1128 v3(2000,1108)
  BOTTOM w5: v3(1269.13,1791.62) 1260.62,1791.62 1234,1765 1234,1655 1221.7,1624.7 1221.7,1333.08 1533.28,1021.5 1619.11,996 1730,996 1735,1001 1735,1015 1740,1020 1748.5,1020 1753.5,1015 1753.5,1001 1758.5,996 1807.84,996 1812.84,1001 1812.84,1016 1817.84,1021 1827.84,1021 1832.84,1016 1832.84,1001 1837.84,996 1846.84,996 1851.84,1001 1851.84,1016.5 1856.84,1021.5 1932.5,1021.5 2000,1089 v3(2000,1108)
PSRAM_A2: U8.H2 U10.A5 | length 1820.5
  TOP w5: v3(1214,1849) 1219.91,1843.09 1243.37,1843.09 U8.H2@1256.46,1830 ; U10.A5@1913.35,1190.71 1921.26,1190.71 1940,1171.97 1940,1145.56 1966,1119.56 1966,1089 2007,1048 v3(2007,1019)
  BOTTOM w5: v3(1214,1849) 1203.5,1838.5 1203.5,1684.8 1200,1678.56 1176.7,1637 1176.7,1314.3 1540,951 1939,951 v3(2007,1019)
PSRAM_A3: U8.J2 U10.B3 | length 1823.7
  TOP w4: v3(1243.79,1817.2) 1256.46,1804.53 U8.J2@1256.46,1804.41
  TOP w5: U10.B3@1883.82,1249.76 1899.58,1234 1926.22,1234 1991,1169.22 1991,1159 2024.85,1125.15 v3(2027,1125.15)
  BOTTOM w4: 1216,1789.41 v3(1243.79,1817.2)
  BOTTOM w5: 1216,1789.41 1216,1676.08 1200,1646.4 1191.7,1631 1191.7,1320.64 1546.34,966 1932,966 2033,1067 2033,1119.15 v3(2027,1125.15)
PSRAM_A4: U8.J3 U10.B4 | length 1632.9
  TOP w4: U8.J3@1282.05,1804.41 1293,1793.46 1293,1793.33 v3(1294.72,1791.61) ; U10.B4@1883.82,1220.24 1899.06,1205 1919,1205 1948.5,1175.5 1948.5,1169.28 1950,1167.78
  TOP w5: 1950,1167.78 1961,1156.78 1961,1145.78 1983,1123.78 v3(1983,1095)
  BOTTOM w5: v3(1294.72,1791.61) 1294.72,1789.72 1280.94,1775.94 1262.99,1775.94 1244,1756.95 1244,1647 1237,1625 1237,1339 1541.2,1034.8 1621.34,1011 1670,1011 1675,1016 1675,1028 1680,1033 1690,1033 1695,1028 1695,1016 1700,1011 1715,1011 1720,1016 1720,1031.5 1725,1036.5 1924.5,1036.5 v3(1983,1095)
PSRAM_A5: U8.K3 U10.C3 | length 1634.6
  TOP w4: v3(1269.27,1740.45) 1269.27,1767.27 1280.82,1778.82 U8.K3@1282.05,1778.82
  TOP w5: v3(1839,1234) 1839,1234.47 U10.C3@1854.29,1249.76
  BOTTOM w5: v3(1269.27,1740.45) 1269.27,1734 1274.27,1729 1304.18,1729 1309.18,1734 1309.18,1745.82 1305.64,1749.36 1282.64,1749.36 1271,1761 1263,1761 1253,1751 1253,1678 1258,1673 1274,1673 1279,1668 1279,1661 1274,1656 1260,1656 1255,1651 1255,1637 1260,1632 1264.95,1632 1269.95,1627 1269.95,1566.05 1283,1553 1283,1487.55 1278,1482.55 1257,1482.55 1252,1477.55 1252,1427.55 1257,1422.55 1278,1422.55 1283,1417.55 1283,1385.5 1278,1380.5 1256.5,1380.5 1252,1376 1252,1345.22 1549.12,1048.1 1603.36,1032 1624,1032 1635,1043 1635,1064 1640,1069 1654.56,1069 1682.06,1096.5 1814.5,1096.5 1820,1102 1820,1186 1825,1191 1848,1191 1853,1196 1853,1228.99 1848,1233.99 v3(1839,1234)
PSRAM_A6: U8.P6 U10.C4 | length 1638.6
  TOP w5: v3(1346.09,1663.6) 1358.82,1676.33 U8.P6@1358.82,1676.46 ; v3(1837.06,1205.75) 1851.55,1220.24 U10.C4@1854.29,1220.24
  BOTTOM w5: 1326.92,1334.5 1319.74,1327.32 1312.68,1327.32 1305.61,1334.39 1305.61,1342.61 1321.53,1358.53 1321.53,1364.47 1313,1373 1313,1567.44 1308,1572.44 1306,1572.44 1299.95,1578.49 1299.95,1588.39 1304,1592.44 1308,1592.44 1313,1597.44 1313,1607 1308,1612 1301,1612 1296,1617 1296,1630 1301,1635 1308,1635 1313,1640 1313,1647 1317,1651 1339,1651 1346.09,1658.09 v3(1346.09,1663.6) ; 1326.94,1334.5 1335.68,1343.24 1342.76,1343.24 1366.81,1319.19 1366.81,1312.11 1351.89,1297.19 1351.89,1290.11 1358.96,1283.04 1366.04,1283.04 1380.96,1297.96 1388.04,1297.96 1395.11,1290.89 1395.11,1283.81 1380.19,1268.89 1380.19,1261.81 1387.26,1254.74 1394.34,1254.74 1409.26,1269.66 1416.34,1269.66 1423.41,1262.59 1423.41,1255.51 1408.49,1240.59 1408.49,1233.51 1415.56,1226.44 1422.64,1226.44 1437.56,1241.36 1444.64,1241.36 1450.96,1235.04 1450.96,1227.96 1435.01,1212.01 1435.01,1204.65 1501.66,1138 1517,1138 1522,1133 1522,1119 1527,1114 1536,1114 1541,1119 1541,1135 1556,1150 1556,1172 1561,1177 1570,1177 1575,1172 1575,1160 1580,1155 1626,1155 1631,1150 1631,1110 1636,1105 1648,1105 1653,1110 1653,1159 1658,1164 1683,1164 1688,1159 1688,1150 1683,1145 1671,1145 1666,1140 1666,1131.51 1671,1126.51 1682.05,1126.51 1785.5,1126.5 1790,1131 1790,1155 1800,1165 1800,1186 1795,1191 1783,1191 1778,1196 1778,1208 1783,1213 1797,1213 1803.4,1219.4 1833,1219.4 1837.06,1215.34 v3(1837.06,1205.75)
PSRAM_A7: U8.N6 U10.D4 | length 1637.2
  TOP w5: v3(1346.09,1689.19) 1358.82,1701.92 U8.N6@1358.82,1702.05 ; v3(1812.11,1204.9) 1824.76,1217.55 U10.D4@1824.76,1220.24
  BOTTOM w5: v3(1346.09,1689.19) 1346.09,1695 1341.09,1700 1315,1700 1310,1695 1310,1685 1315,1680 1327,1680 1331.59,1675.41 1331.59,1668 1326.59,1663 1315,1663 1306.1,1654.1 1306,1654.1 1301,1649.1 1282,1649.1 1277,1644.1 1277,1636 1284.95,1628.05 1284.95,1572.27 1298,1559.22 1298,1469 1293,1464 1271,1464 1267,1460 1267,1445 1271,1441 1293,1441 1298,1436 1298,1369 1293,1364 1274,1364 1269,1359 1269,1349.44 1520.44,1098 1533,1098 1538,1093 1538,1080.44 1543.44,1075 1551,1075 1556,1080 1556,1128 1561,1133 1571,1133 1576,1128 1576,1060 1582,1054 1592.11,1051 1616,1051 1620,1055 1620,1069 1616,1073 1599,1073 1594,1078 1594,1134 1599,1139 1609,1139 1614,1134 1614,1089.01 1619,1084.01 1648.35,1084.01 1675.84,1111.5 1802.5,1111.5 1805,1114 1805,1146.22 1810.36,1151.58 1810.36,1203.15 v3(1812.11,1204.9)
PSRAM_A8: U8.R7 U10.H2 | length 1635.3
  TOP w5: v3(1371.26,1636.74) 1361,1626.48 1361,1585.88 1366.88,1580 1375,1580 1380,1585 1380,1611.22 1387.5,1618.72 1387.5,1645.82 1388,1646.32 1388,1647.87 1385,1650.87 U8.R7@1384.41,1650.87 ; v3(1603,1275) 1606,1278 1668,1278 1673,1283 1673,1293 1668,1298 1653,1298 1648,1303 1648,1316 1653,1321 1673,1321 1684,1332 1684,1347.54 1679,1352.54 1660,1352.54 1655,1357.54 1655,1367.54 1660,1372.54 1674,1372.54 1679,1377.54 1679,1387.54 1674,1392.54 1660,1392.54 1655,1397.54 1655,1407.54 1660,1412.54 1674,1412.54 1679,1417.54 1679,1442 1684,1447 1696,1447 1701,1442 1701,1324 1686.65,1309.65 1686.65,1272 1691.65,1267 1701.65,1267 1706.65,1272 U10.H2@1706.65,1279.29
  BOTTOM w5: v3(1371.26,1636.74) 1371.13,1636.74 1371,1636.61 1353.34,1636.61 1343,1626.27 1343,1387.22 1491.22,1239 1504,1239 1509,1234 1509,1224 1514,1219 1524,1219 1529,1224 1529,1234 1534,1239 1542.76,1239 1555.19,1239.01 1606,1239 1611,1244 1611,1253 1606,1258 1492,1258 1487,1263 1487,1272 1492,1277 1601,1277 v3(1603,1275)
PSRAM_A9: U8.P7 U10.H3 | length 1644.5
  TOP w5: v3(1371.61,1663.54) 1371.61,1663.66 U8.P7@1384.41,1676.46 ; v3(1591.5,1170.5) 1591.5,965 1586.5,960 1571,960 1566,965 1566,1187 1571,1192 1599,1192 1604,1197 1604,1210 1599,1215 1571,1215 1566,1220 1566,1234.22 1571,1239.22 1604,1239.22 1627.78,1263 1676.77,1263 1690.01,1249.76 U10.H3@1706.65,1249.76
  BOTTOM w5: v3(1371.61,1663.54) 1367.54,1663.54 1328,1624 1328,1379.22 1475.73,1231.49 1475.73,1224.41 1459.7,1208.38 1459.7,1201.52 1466.99,1194.23 1473.85,1194.23 1490.77,1211.15 1497.85,1211.15 1503.42,1205.58 1503.42,1198.5 1486.5,1181.58 1486.5,1174.5 1492.46,1168.54 1499.54,1168.54 1510,1179 1516,1179 1521,1174 1521,1156 1526,1151 1535,1151 1540,1156 1540,1178 1554,1192 1624,1192 1629,1187 1629,1175 1624,1170 1592,1170 v3(1591.5,1170.5)
PSRAM_A10: U8.N7 U10.H4 | length 1629.6
  TOP w4: v3(1371.68,1689.19) 1384.41,1701.92 U8.N7@1384.41,1702.05
  TOP w5: v3(1659,1211) 1651,1211 1648,1208 1648,1134 1653,1129 1671,1129 1676,1124 1676,1111 1671,1106 1653,1106 1648,1101 1648,1090 1653,1085 1671,1085 1676,1080 1676,1068.56 1671,1063.56 1659.56,1063.56 1653,1057 1643.22,1057 1634,1066.22 1634,1226.78 1640.22,1233 1667,1233 1679.76,1220.24 U10.H4@1706.65,1220.24
  BOTTOM w5: v3(1371.68,1689.19) 1371.68,1683.98 1381.66,1674 1417,1674 1422,1669 1422,1663 1417,1658 1396,1658 1391,1653 1391,1635 1376.01,1620.01 1362,1620.01 1358,1616.01 1358,1393.44 1467.44,1284 1477.78,1284 1485.78,1292 1608,1292 1626,1274 1626,1252 1631,1247 1655,1247 1660,1242 1660,1232 1655,1227 1642,1227 1639,1224 1548.98,1224 1544,1219.02 1544,1211.98 1548.98,1207 1641,1207 1646,1202 1646,1184 1651,1179 1661,1179 1666,1184 1666,1195 1673.63,1202.63 1673.63,1209.37 1668.87,1214.13 1662.13,1214.13 v3(1659,1211)
PSRAM_A11: U8.M7 U10.H5 | length 1633.1
  TOP w4: v3(1371.55,1714.78) U8.M7@1384.41,1727.64
  TOP w5: v3(1682,1186.5) 1682.5,1187 1702.94,1187 U10.H5@1706.65,1190.71
  BOTTOM w5: v3(1371.55,1714.78) 1371.55,1727 1376.55,1732 1408,1732 1413,1737 1413,1818 1418,1823 1428,1823 1433,1818 1433,1652 1428,1647 1408,1647 1403,1642 1403,1627.66 1373,1597.66 1373,1399.66 1434.66,1338 1481,1338 1486,1343 1486,1351.92 1481,1356.92 1437.08,1356.92 1385.04,1408.96 1385.04,1416.04 1390.46,1421.46 1397.54,1421.46 1444,1375 1482,1375 1492,1365 1515,1365 1527,1353 1527,1349 1532,1344 1569,1344 1574,1339 1574,1330 1569,1325 1464,1325 1459,1320 1459,1313.66 1465.66,1307 1621.34,1307 1641,1287.34 1641,1267 1646,1262 1663,1262 1690.01,1234.99 1690.01,1194.51 v3(1682,1186.5)
PSRAM_A12: U8.L15 U10.G3 | length 1775.9
  TOP w5: U8.L15@1589.13,1753.23 1590.36,1752 1620,1752 1639,1733 1708.99,1733 v2(1745,1696.99) ; v3(1649,1036) 1643,1036 1619,1060 1619,1233 1634,1248 1673,1248 1685,1236 1714,1236 1727.76,1249.76 U10.G3@1736.18,1249.76
  BOTTOM w5: v3(1649,1036) 1658.78,1045.78 1658.78,1052 1688.28,1081.5 1902.94,1081.5 1922.44,1101 1923.05,1101 1966,1143.95 1966,1182.44 2098.5,1314.94 2098.5,1565.5 1997,1667 1774.99,1667 v2(1745,1696.99)
PSRAM_A13: U8.K15 U10.G4 | length 1683.9
  TOP w5: U8.K15@1589.13,1778.82 1596.9,1778.82 1603.02,1772.68 1632.32,1772.68 1640.59,1764.41 1730.59,1764.41 v2(1795,1700) ; v3(1703.43,1050.91) 1707,1054.48 1707,1137 1691,1153 1691,1169.68 1696,1174.68 1711.68,1174.68 1721.44,1184.44 1721.44,1195.44 1736.18,1210.18 U10.G4@1736.18,1220.24
  BOTTOM w5: v3(1703.43,1050.91) 1704.02,1051.5 1915.99,1051.5 1996,1131.51 1996,1170 2162,1336 2162,1546 2011,1697 1798,1697 v2(1795,1700)
PSRAM_A14: U8.K14 U10.F3 | length 1755.6
  TOP w4: 1693,1206.74 1717,1206.74 1722,1211.74 1722,1227 1730,1235 1750.95,1235 U10.F3@1765.71,1249.76
  TOP w5: U8.K14@1563.54,1778.82 1576.4,1765.96 1595.04,1765.96 1599,1762 1626,1762 1638.59,1749.41 1718.59,1749.41 v2(1770,1698) ; v3(1682.44,1050.2) 1682.44,1051.85 1691,1060.41 1691,1131.78 1667,1155.78 1667,1197.07 1676.67,1206.74 1693,1206.74
  BOTTOM w5: v3(1682.44,1050.2) 1682.44,1054.44 1694.5,1066.5 1909.77,1066.5 1981,1137.73 1981,1176.22 2116,1311.22 2116,1569 2113.5,1571.5 2113.5,1571.72 2003.22,1682 1783,1682 1770,1695 v2(1770,1698)
PSRAM_A15: U8.K13 U10.F4 | length 1778.9
  TOP w4: U10.F4@1765.71,1220.24 1780,1234.53 1780,1256 1789,1265 1803,1265 1809.25,1271.25 1809.25,1318.25 1821.5,1330.5
  TOP w5: U8.K13@1537.95,1778.82 1550.45,1791.32 1599.37,1791.32 1608.78,1781.91 v2(1685,1781.91) ; 1821.5,1330.5 1821.5,1361.5 1854,1394 1854,1447 1862,1455 v2(2007,1455)
  BOTTOM w5: v2(1685,1781.91) 1705.09,1781.91 1727,1760 1727,1689 1769,1647 1814,1647 1819,1642 1819,1617 1809,1607 1809,1588 1814,1583 1824,1583 1829,1588 1829,1600 1834,1605 1843.9,1605 1848.9,1600 1848.9,1549 1853.9,1544 1863.9,1544 1868.9,1549 1868.9,1589 1873.9,1594 1909,1594 1914,1589 1914,1510 1919,1505 1928,1505 1933,1510 1933,1614 1938,1619 1951,1619 1956,1614 1956,1442 1961,1437 1975,1437 1980,1442 1980,1557 1985,1562 1996,1562 2001,1557 2001,1460 2006,1455 v2(2007,1455)
PSRAM_A16: U8.N14 U10.E4 | length 1633
  TOP w5: U8.N14@1563.54,1702.05 1571.45,1702.05 1584.54,1688.96 1594.31,1688.96 1601.63,1681.64 1601.63,1681.51 1613.14,1670 1618.78,1670 1623.49,1674.71 1633.72,1674.71 1637.01,1678 1682.53,1678 1687.53,1673 1687.53,1604.5 1692.53,1599.5 1813.5,1599.5 v2(1839,1625) ; U10.E4@1795.24,1220.24 v3(1810,1235)
  BOTTOM w5: v3(1810,1235) 1824,1249 1859,1249 1864,1244 1864,1189.81 1855.35,1181.16 1855.35,1181 1850.35,1176 1840,1176 1835,1171 1835,1101.5 1840,1096.5 1896.72,1096.5 1951,1150.78 1951,1190 2083.5,1322.5 2083.5,1421 2078.5,1426 2045,1426 2040,1431 2040,1442.15 2045,1447.15 2078,1447.15 2083,1452.15 2083,1462.15 2078,1467.15 2045,1467.15 2040,1472.15 2040,1573.25 2018.25,1595 2002,1595 1997,1600 1997,1645.78 1990.78,1652 1844,1652 1839,1647 v2(1839,1625)
PSRAM_A17: U8.N13 U10.D3 | length 1699
  TOP w4: U10.D3@1824.76,1249.76 1840,1265 1950,1265
  TOP w5: U8.N13@1537.95,1702.05 1542.95,1702.05 1555.45,1689.55 1568.13,1689.55 1576.04,1681.64 1576.04,1671.87 1583.95,1663.96 1593.72,1663.96 1614.5,1643.18 1614.5,1634.57 1623.57,1625.5 1633.44,1625.5 1638.44,1620.5 1638.44,1589 1643.44,1584 1827,1584 v2(1866,1623) ; 1950,1265 2030,1265 2035,1270 2035,1291 2030,1296 v3(1965,1296)
  BOTTOM w5: v2(1866,1623) 1866,1633 1870,1637 1978,1637 1982,1633 1982,1581.53 1986.53,1577 2010,1577 2025,1562 2025,1433.47 2020,1428.47 1998,1428.47 1993,1423.47 1993,1413.47 1998,1408.47 2059,1408.47 2064,1403.47 2064,1393.47 2059,1388.47 1998,1388.47 1993,1383.47 1993,1373.47 1998,1368.47 2053,1368.47 2058,1363.47 2058,1353.47 2053,1348.47 1998,1348.47 1993,1343.47 1993,1333.47 1998,1328.47 2043,1328.47 2048,1323.47 2048,1310 2043,1305 1994,1305 1989,1300 1989,1265 1984,1260 1970,1260 1965,1265 v3(1965,1296)
PSRAM_NBL0: U8.A4 U10.A1 | length 2095
  TOP w5: v3(1295.26,2057.26) 1305.73,2046.79 1305.73,2011.04 U8.A4@1307.64,2009.13 ; U10.A1@1913.35,1308.82 1914.82,1308.82 v3(1964,1358)
  L4_SIG w4: v3(1295.26,2057.26) 1304,2057.26 1309,2062.26 1309,2145 1314,2150 1337,2150 1342,2145 1342,2062.26 1347,2057.26 1354,2057.26 1359,2062.26 1359,2149 1364,2154 1372,2154 1377,2149 1377,2062.26 1382,2057.26 1411,2057.26 1416,2062.26 1416,2129 1421,2134 1455,2134 1460,2129 1460,2018 1431,1989 1431,1915 1423,1907 1423,1677 1443,1657 1491.68,1657 1535,1613.68 1535,1610.2 1543.2,1602 1554.8,1602 1562.28,1609.48 1578.53,1609.48 1586.73,1601.28 1586.73,1549.67 1616,1520.4 1616,1520.3 1617.49,1518.81 1617.49,1464.51 1629,1453 1862,1453 1886,1429 1886,1401 1891,1396 1903,1396 1908,1401 1908,1428 1913,1433 1965,1433 2008,1390 2008,1363 2003,1358 v3(1964,1358)
PSRAM_NBL1: U8.A3 U10.B2 | length 2090.4
  TOP w5: v3(1275.03,2035.03) v3(1275.03,2035.03) 1282.05,2027.95 U8.A3@1282.05,2009.13 ; U10.B2@1883.82,1279.29 1899.53,1295 1899.53,1316.64 v3(1962.89,1380)
  L4_SIG w4: v3@1275.06,2035 1305,2035 1315,2045 1397,2045 1402,2040 1402,2024 1423,2003 1423,1921 1413,1911 1413,1672 1440,1645 1483.19,1645 1534.19,1594 1553.15,1594 1565.68,1581.47 1570.33,1581.47 1574.18,1577.62 1574.18,1545.24 1604,1515.42 1604,1348.69 1608.69,1344 1615.31,1344 1620,1348.69 1620,1436 1625,1441 1631,1441 1636,1436 1636,1348.69 1640.69,1344 1647.31,1344 1652,1348.69 1652,1436 1657,1441 1663,1441 1668,1436 1668,1348.69 1672.69,1344 1679.31,1344 1684,1348.69 1684,1436.31 1688.69,1441 1695.31,1441 1700,1436.31 1700,1386.69 1704.69,1382 1711.31,1382 1716,1386.69 1716,1436 1721,1441 1857,1441 1874,1424 1874,1385 1879,1380 v3(1962.89,1380)
PSRAM_NE1: R65.1 U8.A11 | length 1764.3
  TOP w5: U8.A11@1486.77,2009.13 1486.77,2028.14 v3(1488.63,2030) ; R65.1@2020,919.49 2054.49,919.49 2066,931 2066,1565.5 v2(2064.5,1567)
  L4_SIG w4: v3(1488.63,2030) 1488.63,2069 1493.63,2074 1504.53,2074 1509.53,2069 1509.53,1888.47 1544,1854 1600,1812.41 1712.77,1812.41 1716.77,1816.41 1716.77,1839 1720.77,1843 1728.77,1843 1732.77,1839 1732.77,1816.41 1736.77,1812.41 1744.77,1812.41 1748.77,1816.41 1748.77,1839 1752.77,1843 1760.77,1843 1764.77,1839 1764.77,1816.41 1768.77,1812.41 1794.59,1812.41 1895,1712 1955,1712 2066.5,1600.5 2066.5,1569 v2(2064.5,1567)
PWR_ENN: R20.1 U1.3 U2.28 | length 355.3
  TOP w10: U2.28@1966.26,2975.79 2000.79,2975.79 2025,3000 2130,3000 2185,3055 R20.1@2215,3055
  TOP w20: R20.1@2215,3055 2220,3050 U1.3@2286.7,3050
PWR_EXT: R4.1 R5.1 R6.2 U2.39 | length 159.6
  TOP w10: U2.39@1863.9,3196.26 1863.9,3238.9 R6.2@1890,3265
  TOP w20: R4.1@1810,3265 R5.1@1850,3265 R6.2@1890,3265
QSPI_CLK: U5.6 U6.6 U8.M6 | length 2309.2
  TOP w5: U6.6@1240,2746.84 1240,2773 1257,2790 v2(1257,2806) ; v3(1346.09,1740.5) 1346.09,1740.37 U8.M6@1358.82,1727.64 ; v2(1482,2791) 1485,2788 U5.6@1485,2748.54
  L4_SIG w4: v3(1346.09,1740.5) 1355,1749.41 1355,1820.39 1361,1826.39 1361,1859.2 1355,1865.2 1355,1898 1369,1912 1402.68,1912 1414,1923.32 1414,1988 1387,2015 1275.26,2015 1261.03,2029.23 1261.03,2041.03 1275,2055 1275,2105 1289,2119 1289,2224 1320,2255 1460,2255 1540,2335 1730,2335 1780,2385 1780,2644 1727.62,2696.38 1727.62,2742.62 v2(1745,2760)
  BOTTOM w5: v2(1257,2806) 1314,2806 1351,2769 1460,2769 v2(1482,2791) 1496,2805 1710.24,2805 1745,2770.24 v2(1745,2760)
QSPI_D0: U5.5 U6.5 U8.F14 | length 1672.6
  TOP w5: U6.5@1290,2746.84 v2(1290,2782) ; v2(1530,2782) 1535,2777 U5.5@1535,2748.54 ; v3(1550.62,1893.98) 1563.42,1881.18 U8.F14@1563.54,1881.18
  L4_SIG w4: v3(1550.62,1893.98) 1550.62,1895.62 1603.3,1948.3 1603.3,1972.35 1621.95,1991 1780,1991 1800,2011 1800,2305 1848,2353 1848,2602 v2(1785,2665)
  BOTTOM w5: v2(1290,2782) 1304,2782 1337,2749 1497,2749 v2(1530,2782) 1668,2782 v2(1785,2665)
QSPI_D1: U5.2 U6.2 U8.B14 | length 870.2
  TOP w5: v2(1189.68,2406.7) 1190,2407.02 U6.2@1190,2439.76 ; U5.2@1435,2441.46 v2(1435,2408) 1435,2405 1495,2345 1495,2300 1588.4,2206.6 1588.4,2086.17 1599.96,2074.61 1599.96,2037.64 1576.63,2014.31 1576.63,2004.54 1563.54,1991.45 U8.B14@1563.54,1983.54
  BOTTOM w5: v2(1189.68,2406.7) 1190.7,2406.7 1227,2443 1317,2443 1375,2385 1415,2385 1435,2405 v2(1435,2408)
QSPI_D2: U5.3 U6.3 U8.A2 | length 806.2
  TOP w5: U6.3@1240,2439.76 v2(1240,2405) 1240,2385 1195,2340 1195,2105 1222,2078 1230.43,2078 1241.5,2066.93 1241.5,2031.23 1255,2017.73 1255,2010.59 U8.A2@1256.46,2009.13 ; v2(1480,2405) 1485,2410 U5.3@1485,2441.46
  BOTTOM w5: v2(1240,2405) 1263,2428 1308.22,2428 1366.22,2370 1445,2370 v2(1480,2405)
QSPI_D3: U5.7 U6.7 U8.M15 | length 2675.5
  TOP w5: U6.7@1190,2746.84 1190,2760 1228,2798 v2(1228,2811) ; U5.7@1435,2748.54 1435,2770 1455,2790 v2(1455,2793) ; U8.M15@1589.13,1727.64 1594.35,1727.64 1607,1715 1702,1715 1739.5,1677.5 1819.5,1677.5 1847,1705 1915,1705 1990,1780 v2(1990,1830)
  L4_SIG w4: v2(1455,2793) 1482,2820 1525,2820 1629,2924 2046.65,2924 2070,2900.65 2070,2839 2021,2790 2021,1861 v2(1990,1830)
  BOTTOM w5: v2(1228,2811) 1242,2825 1322,2825 1354,2793 v2(1455,2793)
QSPI_NCS: R30.1 U5.1 U6.1 U8.B6 | length 803
  TOP w5: v2(1140,2406.76) U6.1@1140,2439.76 ; U8.B6@1358.82,1983.54 1346.32,1996.04 1346.32,2029.37 1350.73,2033.78 1350.73,2053.73 1369.49,2072.49 1369.49,2106.31 1381.5,2118.32 1381.5,2203.33 1385,2206.83 R30.1@1385,2380 v2(1385,2408.46) U5.1@1385,2441.46
  BOTTOM w5: v2(1140,2406.76) 1196.24,2463 1322,2463 1376.54,2408.46 v2(1385,2408.46)
REXT_OTGPHY: R54.1 U8.J15 | length 274.4
  TOP w5: U8.J15@1589.13,1804.41 1592.54,1801 1604.69,1801 1608.78,1796.91 1623.64,1796.91 1626.22,1799.49 1770.51,1799.49 1780,1790 1780,1784 1785,1766 1791,1760 1805,1760 R54.1@1825,1740
SAI2_FS_A: TP11.1 U7.E3 U8.C2 | length 1069.6
  TOP w5: U7.E3@614.84,2300.63 v4(621.14,2294.33) ; TP11.1@615,2070 615,2065 v2(645,2035) 660,2020 780,2020 845,2085 997.5,2085 1009.48,2073.02 1009.48,2059.97 1021.95,2047.5 1144.79,2047.5 1159,2033.29 1159,2026 1200,1985 1210,1985 1224,1971 1243.41,1971 U8.C2@1256.46,1957.95
  L4_SIG w4: v4(621.14,2294.33) 609,2282.19 609,2256 675,2190 675,2065 v2(645,2035)
SAI2_I2C1_SCL: R39.1 R44.2 U8.A5 | length 745.3
  TOP w5: R39.1@827,2201 827,2221.5 840.5,2235 v2(840.5,2235.67) ; R44.2@1310,2125 1302.5,2117.5 1302.5,2108.28 1293,2098.78 v3(1293,2093.94) 1298.94,2088 1312.15,2088 1335.73,2064.42 1335.73,2033.78 1333.23,2031.28 U8.A5@1333.23,2009.13
  BOTTOM w5: v2(840.5,2235.67) 854.83,2250 1178,2250 1213.5,2214.5 1228.08,2214.5 1242.5,2200.08 1242.5,2160.96 1272,2131.46 1272,2121 1293,2100 v3(1293,2093.94)
SAI2_I2C1_SDA: R35.1 R42.2 U8.B4 | length 742
  TOP w5: R35.1@830,2265 860,2265 879,2246 879,2219.24 866.76,2207 v2(865,2207) ; R42.2@1220,2125 1220,2102.5 v3(1225,2097.5) 1229.5,2093 1236.65,2093 1252.65,2077 1261.93,2077 1273,2065.93 1273,2057.58 1294.55,2036.03 1294.55,1996.63 U8.B4@1307.64,1983.54
  BOTTOM w5: v2(865,2207) 874.12,2207 887.12,2220 1163.58,2220 1173.5,2210.08 1173.5,2187.52 1224,2137.02 1224,2098.5 v3(1225,2097.5)
SAI2_INT: U7.G3 U8.B7 | length 1181
  TOP w4: U8.B7@1384.41,1983.54 1396.41,1995.54 1396.41,2014.11 1394,2016.52 1394,2051 1411.1,2068.1 1411.1,2070
  TOP w5: U7.G3@654.21,2300.63 v4(660.51,2294.33) ; 1411.1,2070 1411.1,2084.28 1427.5,2100.68 1427.5,2309.46 v2(1425.96,2311)
  BOTTOM w5: v4(660.51,2294.33) 664.05,2290.79 705.79,2290.79 785,2370 1227.76,2370 1241.76,2356 1318.86,2356 1338.86,2336 1376,2336 1401,2311 v2(1425.96,2311)
SAI2_MCLK_A: TP6.1 U7.D3 U8.D4 | length 1174.9
  TOP w5: v4(588.86,2294.33) U7.D3@595.16,2300.63 ; TP6.1@615,2140 648.21,2106.79 v2(648.21,2081.07) ; v3(1294.97,1945.15) 1302.56,1937.56 1302.56,1937.44 U8.D4@1307.64,1932.36
  L4_SIG w4: v4(588.86,2294.33) 598,2285.19 598,2250.02 663,2185.02 663,2095.86 v2(648.21,2081.07)
  BOTTOM w5: v2(648.21,2081.07) 802.45,2081.07 856.38,2135 865.78,2135 905.78,2175 1075,2175 1126,2124 1173.36,2124 1179,2118.36 1179,2078.56 1195.5,2062.06 1195.5,2047.85 1213.35,2030 1231.78,2030 1236.79,2024.99 1280.28,1981.51 1280.28,1959.84 v3(1294.97,1945.15)
SAI2_SCK_A: TP7.1 U7.G1 U8.C4 | length 916.7
  TOP w5: U7.G1@654.21,2261.26 654.21,2234.79 740,2149 TP7.1@740,2140 740,2125 755,2110 v2(760,2110) ; v3(1294.78,1970.81) U8.C4@1307.64,1957.95
  BOTTOM w5: v2(760,2110) 773.41,2110 837.91,2174.5 884.06,2174.5 899.56,2190 1081.22,2190 1107.72,2163.5 1155.08,2163.5 1194,2124.58 1194,2084.78 1210.5,2068.28 1210.5,2054.07 1219.57,2045 1238,2045 1294.78,1988.22 v3(1294.78,1970.81)
SAI2_SD_A: TP12.1 U7.E4 U8.C3 | length 1148.5
  TOP w5: U7.E4@614.84,2320.31 v4(621.14,2314.01) ; v2(715,2110) 715,2095 TP12.1@740,2070 ; v3(1226,2060.5) 1225.5,2060 1225.5,2034.5 1243.38,2016.62 1243.38,2004.53 1251.29,1996.62 1261.06,1996.62 1268.96,1988.72 1268.96,1971.04 U8.C3@1282.05,1957.95
  L4_SIG w4: v4(621.14,2314.01) 660.99,2314.01 775,2200 775,2170 v2(715,2110)
  BOTTOM w5: v2(715,2110) 725,2110 742.5,2127.5 769.69,2127.5 831.69,2189.5 877.84,2189.5 893.34,2205 1087.44,2205 1113.94,2178.5 1161.3,2178.5 1209,2130.8 1209,2091 1226,2074 v3(1226,2060.5)
SAI2_SD_B: TP4.1 U7.F2 U8.B10 | length 1257.4
  TOP w4: U8.B10@1461.18,1983.54 1474.63,1996.99 1474.63,2040
  TOP w5: U7.F2@634.53,2280.94 v4(640.83,2274.64) ; v2(1462,2305) 1465,2302 TP4.1@1465,2255 1465,2190 1497,2158 1497,2085.3 1487,2075.3 1487,2052.37 1474.63,2040
  BOTTOM w5: v4(640.83,2274.64) 656.47,2259 695.22,2259 791.22,2355 1221.54,2355 1235.54,2341 1312.64,2341 1333.64,2320 1368,2320 1394.5,2293.5 1450.5,2293.5 v2(1462,2305)
STLINK_RX: SB9.2 U2.13 | length 101.8
  TOP w5: U2.13@1686.73,2853.74 1686.73,2799.27 1696.19,2789.81 SB9.2@1696.19,2755.83
STLINK_TX: SB8.2 U2.12 | length 161.9
  TOP w5: U2.12@1623.74,2916.73 1626.19,2914.28 SB8.2@1626.19,2755.83
STM_JTCK: CN2.2 U2.37 | length 1156
  TOP w5: U2.37@1903.27,3196.26 1903.27,3213.27 1920,3230 v2(1939.7,3230)
  L4_SIG w4: v2(1939.7,3230) 1940,3230 1984,3186 2019,3186 2033,3200 2055,3200 2400,3545 2400,3700 2454,3754 2637.64,3754 CN2.2@2675.41,3716.23
STM_JTMS: CN2.4 U2.34 | length 877.1
  TOP w5: U2.34@1966.26,3093.9 2018.9,3093.9 2070,3145 v2(2070,3175)
  L4_SIG w4: v2(2070,3175) 2070,3190 2417,3537 2417,3680 2453.23,3716.23 CN2.4@2475.41,3716.23
STM_RST: C7.2 R24.1 SB6.2 U2.7 | length 186.8
  TOP w5: SB6.2@1496.19,2935.83 1500.36,2940 R24.1@1550,2940 C7.2@1550,2985 1580.16,3015.16 U2.7@1623.74,3015.16
STMOD+_ADC_DAC: P1.13 SB28.1 | length 167.3
  BOTTOM w5: SB28.1@2753.01,2579.67 2865.93,2579.67 P1.13@2904.37,2618.11
STMOD+_I2C2_SCL: P1.7 SB25.2 | length 81.1
  BOTTOM w5: SB25.2@2745.83,2936.19 2822.51,2936.19 P1.7@2825.63,2933.07
STMOD+_I2C2_SDA: P1.10 SB27.2 | length 67.4
  BOTTOM w5: 2760,3165 2821.34,3165 P1.10@2825.63,3169.29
